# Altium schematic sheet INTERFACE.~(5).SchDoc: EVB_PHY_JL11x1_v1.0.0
size A4; Revision: V1.0.0; SheetNumber: 2; SheetTotal: 3; Release Date: 2014-05-28; SchModifyDate: 2020.11.1; PCBVersion: V1.0.0; PCBPartNumber: EVB_PHY_SZ18201; 版本号: V1.0.0
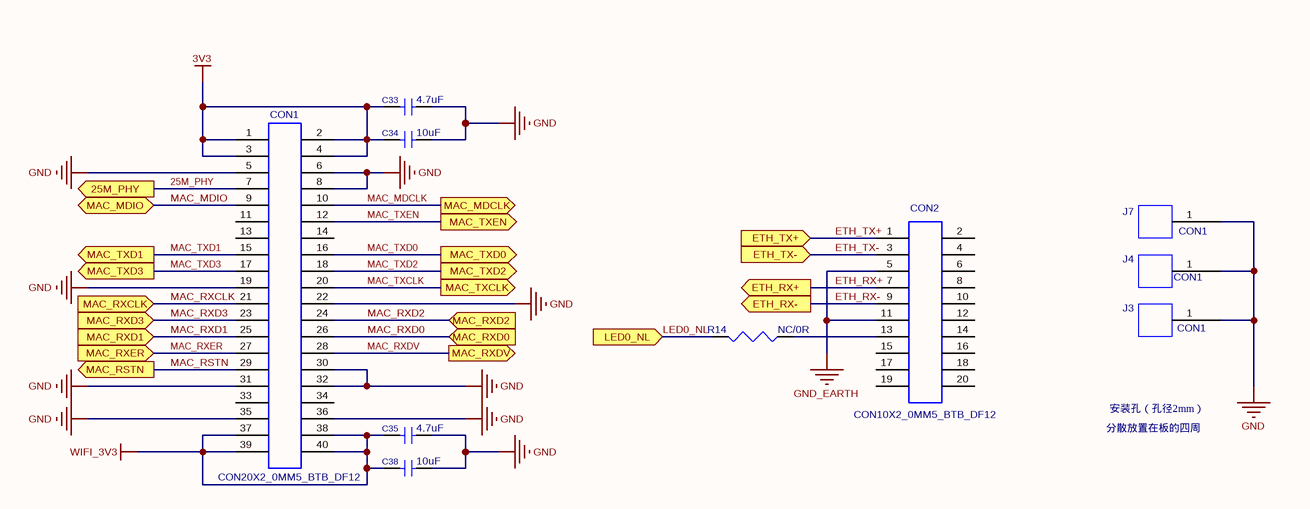
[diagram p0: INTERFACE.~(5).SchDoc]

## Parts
C33  4.7uF  [C0603]
C34  10uF  [C0805]
C35  4.7uF  [C0603]
C38  10uF  [C0805]
CON1  CON20X2_0MM5_BTB_DF12  [CON20X2_0MM5_BTB_DF12_N]
CON2  CON10X2_0MM5_BTB_DF12  [CON10X2_0MM5_BTB_DF12_N]
J3  CON1  [H_2MM2_4MM]
J4  CON1  [H_2MM2_4MM]
J7  CON1  [H_2MM2_4MM]
R14  NC/0R  [R0603]

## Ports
25M_PHY (out), ETH_RX+ (out), ETH_RX- (out), ETH_TX+ (in), ETH_TX- (in), LED0_NL (in), MAC_MDCLK (out), MAC_MDIO (bidir), MAC_RSTN (out), MAC_RXCLK (in), MAC_RXD0 (in), MAC_RXD1 (in), MAC_RXD2 (in), MAC_RXD3 (in), MAC_RXDV (out), MAC_RXER (in), MAC_TXCLK (out), MAC_TXD0 (out), MAC_TXD1 (out), MAC_TXD2 (out), MAC_TXD3 (out), MAC_TXEN (out)

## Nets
3V3: C33.1 C34.1 CON1.1 CON1.2 CON1.3 CON1.4
GND: C33.2 C34.2 C35.2 C38.2 CON1.5 CON1.6 CON1.8 CON1.19 CON1.22 CON1.30 CON1.31 CON1.32 CON1.35 CON1.36 J3.1 J4.1 J7.1
GND_EARTH: CON2.5 CON2.11
WIFI_3V3: C35.1 C38.1 CON1.37 CON1.38 CON1.39 CON1.40
25M_PHY: CON1.7 ; port 25M_PHY
ETH_RX+: CON2.7 ; port ETH_RX+
ETH_RX-: CON2.9 ; port ETH_RX-
ETH_TX+: CON2.1 ; port ETH_TX+
ETH_TX-: CON2.3 ; port ETH_TX-
LED0_NL: R14.2 ; port LED0_NL
MAC_MDCLK: CON1.10 ; port MAC_MDCLK
MAC_MDIO: CON1.9 ; port MAC_MDIO
MAC_RSTN: CON1.29 ; port MAC_RSTN
MAC_RXCLK: CON1.21 ; port MAC_RXCLK
MAC_RXD0: CON1.26 ; port MAC_RXD0
MAC_RXD1: CON1.25 ; port MAC_RXD1
MAC_RXD2: CON1.24 ; port MAC_RXD2
MAC_RXD3: CON1.23 ; port MAC_RXD3
MAC_RXDV: CON1.28 ; port MAC_RXDV
MAC_RXER: CON1.27 ; port MAC_RXER
MAC_TXCLK: CON1.20 ; port MAC_TXCLK
MAC_TXD0: CON1.16 ; port MAC_TXD0
MAC_TXD1: CON1.15 ; port MAC_TXD1
MAC_TXD2: CON1.18 ; port MAC_TXD2
MAC_TXD3: CON1.17 ; port MAC_TXD3
MAC_TXEN: CON1.12 ; port MAC_TXEN
NetCON2_13: CON2.13 R14.1

Not connected (* = marked no-connect by the designer): CON1 11 13 14 33 34; CON2 2 4 6 8 10 12 14 15 16 17 18 19 20

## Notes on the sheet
- 分散放置在板的四周
- 安装孔（孔径2mm）

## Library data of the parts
C33 C35 = CC0304752XX: C/C,4.7uF,10V +/-10%,0603; Catalog: 陶瓷电容
C34 C38 = CC0501063XX: C/C,10uF,16V,+/-20%,0805; Catalog: 陶瓷电容
CON1 = CNBBM4000XX: 0.5mm ，BTB2*20Pin，SMT，公座，H3.0，DF12#(3.0)-40DS-0.5; PCB DECAL: CON20X2_0MM5_BTB_DF12_BOTTOM; Catalog: Connector
CON2 = CNBBM2000XX: 0.5mm ，BTB2*10Pin，SMT，公座，H3.0，DF12#(3.0)-20DS-0.5; PCB DECAL: CON10X2_0MM5_BTB_DF12_BOTTOM; Catalog: Connector
J3 J4 J7 = CON1: Source_Path: D:\CADENCE\SPB_16.3\TOOLS\CAPTURE\LIBRARY\CONNECTOR.OLB
R14 = CR0300000XX: Res,0R,1/10W,+/-5%,0603; Remark: NC; Catalog: 贴片电阻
